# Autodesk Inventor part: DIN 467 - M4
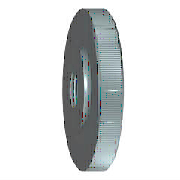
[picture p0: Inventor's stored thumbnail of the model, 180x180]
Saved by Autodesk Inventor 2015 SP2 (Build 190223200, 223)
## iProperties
Created: 2014-02
Part Number: DIN 467 - M4
Material: Stahl, weich
Description: Rändelmutter
Document SubType Name: Modeling
Standard: DIN 467
Designer: ryll
Standards Organization: DIN
Language: de-DE
Size Designation: M4
Categories: <MemberInstance><Categories><Category DisplayName="Verbindungselemente" InternalName="e4da775c-781d-43d5-af7c-5136215cf5a6" Mnemonic="FSTN"><Category DisplayNam
Density: 7.85 g/cm^3
Appearance: Halbpoliert
IsCustomPart: 0
Author: ryll
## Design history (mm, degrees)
body "Solid1"
revolve "Körper" stored, may be unused: angle "d8" = 90 deg
sketch "Skizze2"
  geometry: L1 (0, 0)-(0, 8); L2 (-0.25, 7.996)-(0, 7.746); L3 (0.25, 7.996)-(0, 7.746); C1 r 4 at (0, 0) reference; A1 r 8 centre (0, 0) between (0, 8) and (-0.25, 7.996) reference; A2 r 8 centre (0, 0) between (0.25, 7.996) and (-0.25, 7.996); 1 further point
  constraints: 6 end point, 5 point on circle, 1 centre point, 1 coincident, 1 point on line, 1 symmetric about line, 1 vertical, 1 other
  dimensions: "d4" = 90 deg angle of L3 L2; "d5" = 0.25 distance from line of L1 L2.start (= 0.5 x T)
chamfer "Fase1" distance "d13" = 0.4 (= PHH); stored, may be unused: angle "d15" = 45 deg (= FAWI), second distance "d36" = 0.4 (= PHH)
chamfer "Fase2" distance "d23" = 0.4 (= PHH); stored, may be unused: angle "d24" = 45 deg (= FAWI), second distance "d37" = 0.4 (= PHH)
extrude "Nut1" cut sketch "Skizze2" taper "d6" = 0 deg; stored distance "d11" = 10
pattern_circular "Nuten1" dims angle "d9" = 360 deg
hole "Gewinde" sketch "Skizze2" diameter "d16" = 3.242; stored, may be unused: countersink angle "d20" = 82 deg, drill point angle "d22" = 118 deg; dims "d17" = 6, "d18" = 4, "d19" = 2, "d21" = 8
chamfer "Fase3" distance "d10" = 0.37889 (= -0.5 x GD1 + 0.5 x NND); stored, may be unused: angle "d12" = 30 deg, second distance "d38" = 0.37889 (= -0.5 x GD1 + 0.5 x NND)
workaxis "Work Axis1"
workplane "Work Plane1"
sketch "Skizze1"
  geometry: L1 (0, 0)-(-4, 0) reference; L2 (0, 0)-(0, 8) reference; L3 (0, 8)-(-3.5, 8); L4 (-3.5, 8)-(-3.5, 4.5); L5 (-4, 4)-(-4, 4); L6 (-4, 4)-(-4, 0); A1 r 0.5 centre (-4, 4.5) between (-4, 4) and (-3.5, 4.5)
  constraints: 12 end point, 5 perpendicular, 2 horizontal, 2 point on circle, 2 tangent, 1 centre point, 1 point on line, 1 vertical
  dimensions: "d0" = 0.5 radius of A1 (= RR); "d1" = 4 distance of L1.start L1.end (= KOH); "d2" = 16 diameter of L3 L1 (= KOD); "d3" = 8 diameter of L5.end L1 (= BDM)
other parameters: "FAWI" = 45 deg [user parameter; used in 2 equation terms], "T" = 0.5 [user parameter; used in 2 equation terms], "NND" = 4 [user parameter; used in 2 equation terms], "KOD" = 16 [user parameter; used in 2 equation terms], "KOH" = 4 [user parameter; used in 1 equation term], "KOH1" = 3.5 [user parameter], "BDM" = 8 [user parameter; used in 1 equation term], "PHH" = 0.4 [user parameter; used in 4 equation terms], "GD1" = 3.24223 (computed from THREADDIA, PTC, TOA) [user parameter; used in 2 equation terms], "d25" = 0, "d26" = 0, "RR" = 0.5 [user parameter; used in 1 equation term], "d27" = 0, "d39" = 0, "GUL" = 0.37889 (= 0.541266 x PTC) [user parameter], "THREADDIA" = 4 [user parameter; used in 1 equation term], "TOA" = 30 deg [user parameter; used in 1 equation term], "TPU" = 14.28571 (computed from PTC) [user parameter], "PTC" = 0.7 [user parameter; used in 4 equation terms], "GAL" = 0.37889 (= 0.541266 x PTC) [user parameter]
